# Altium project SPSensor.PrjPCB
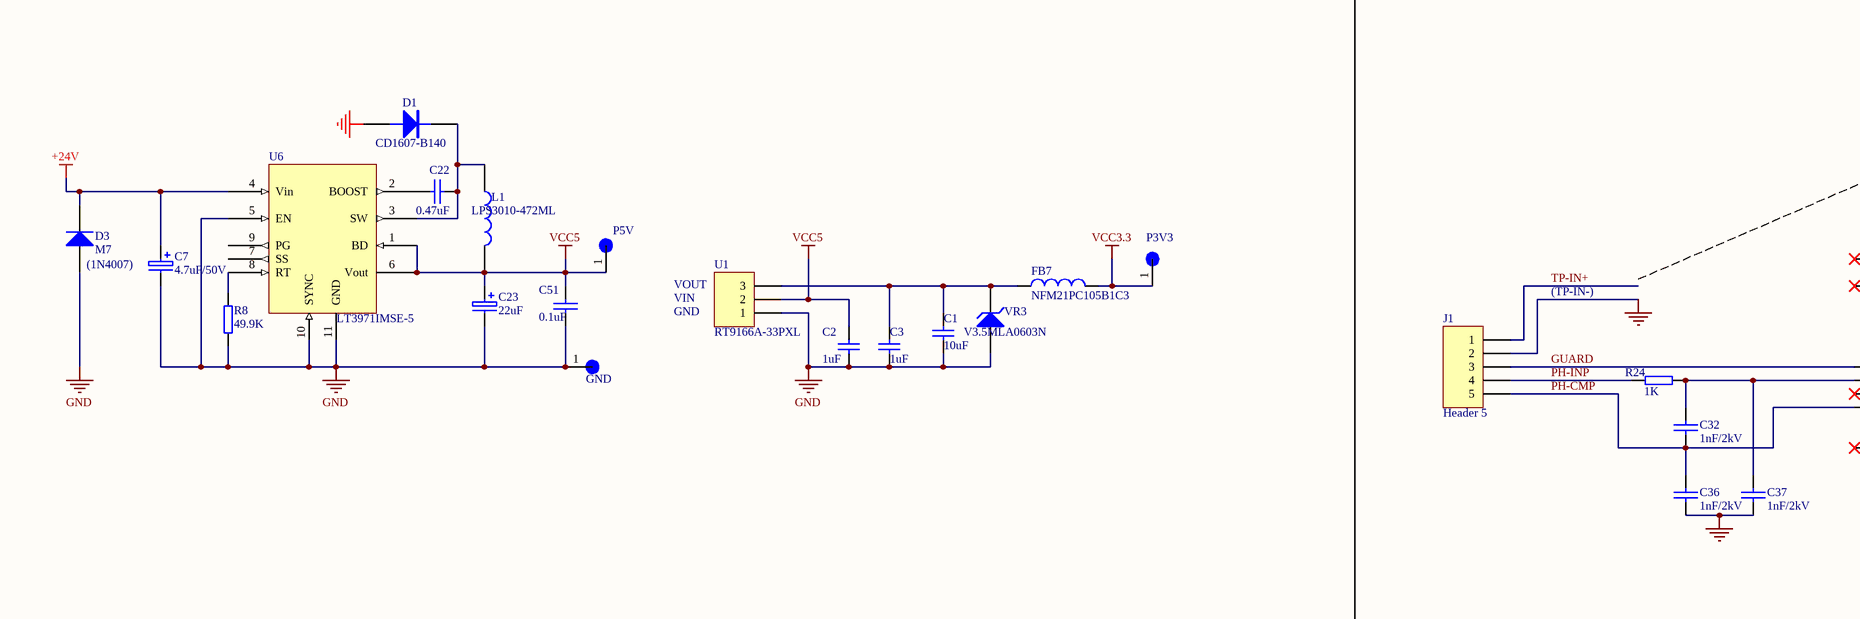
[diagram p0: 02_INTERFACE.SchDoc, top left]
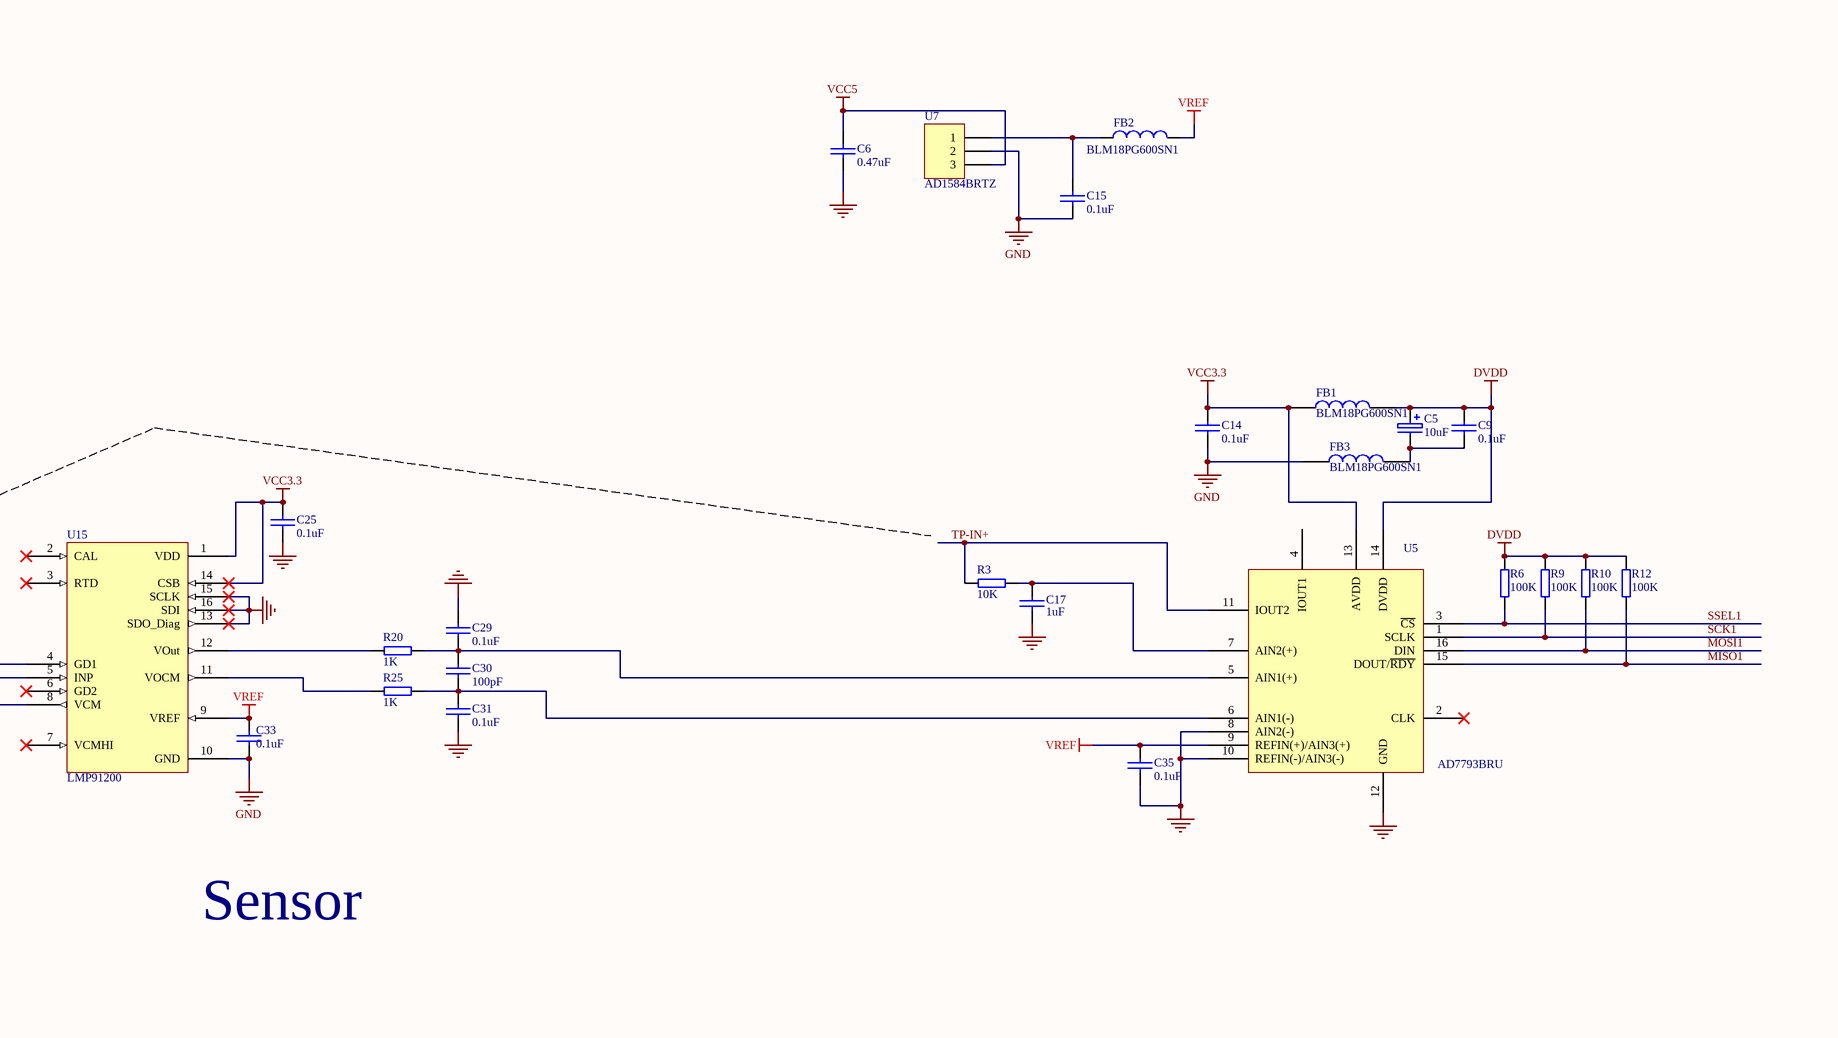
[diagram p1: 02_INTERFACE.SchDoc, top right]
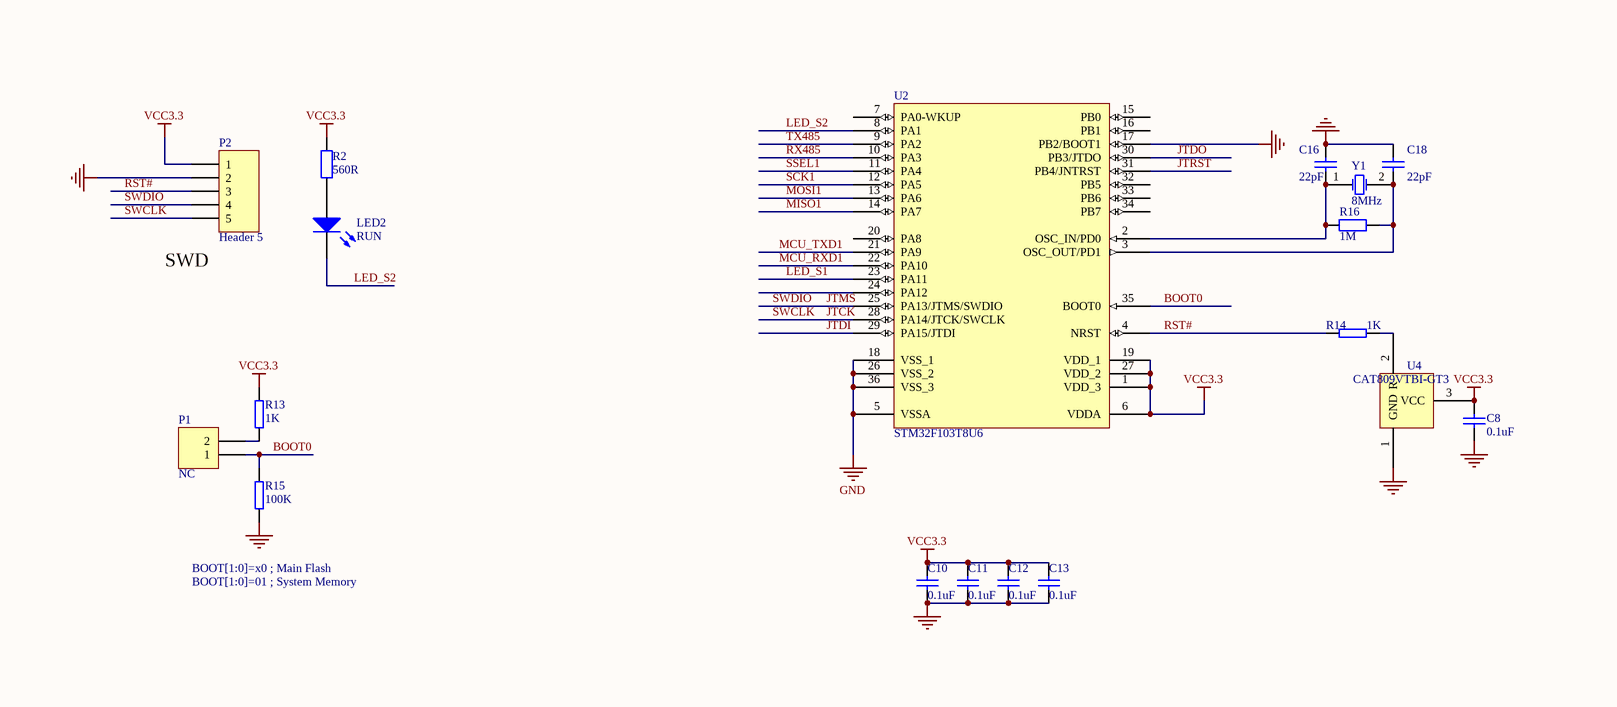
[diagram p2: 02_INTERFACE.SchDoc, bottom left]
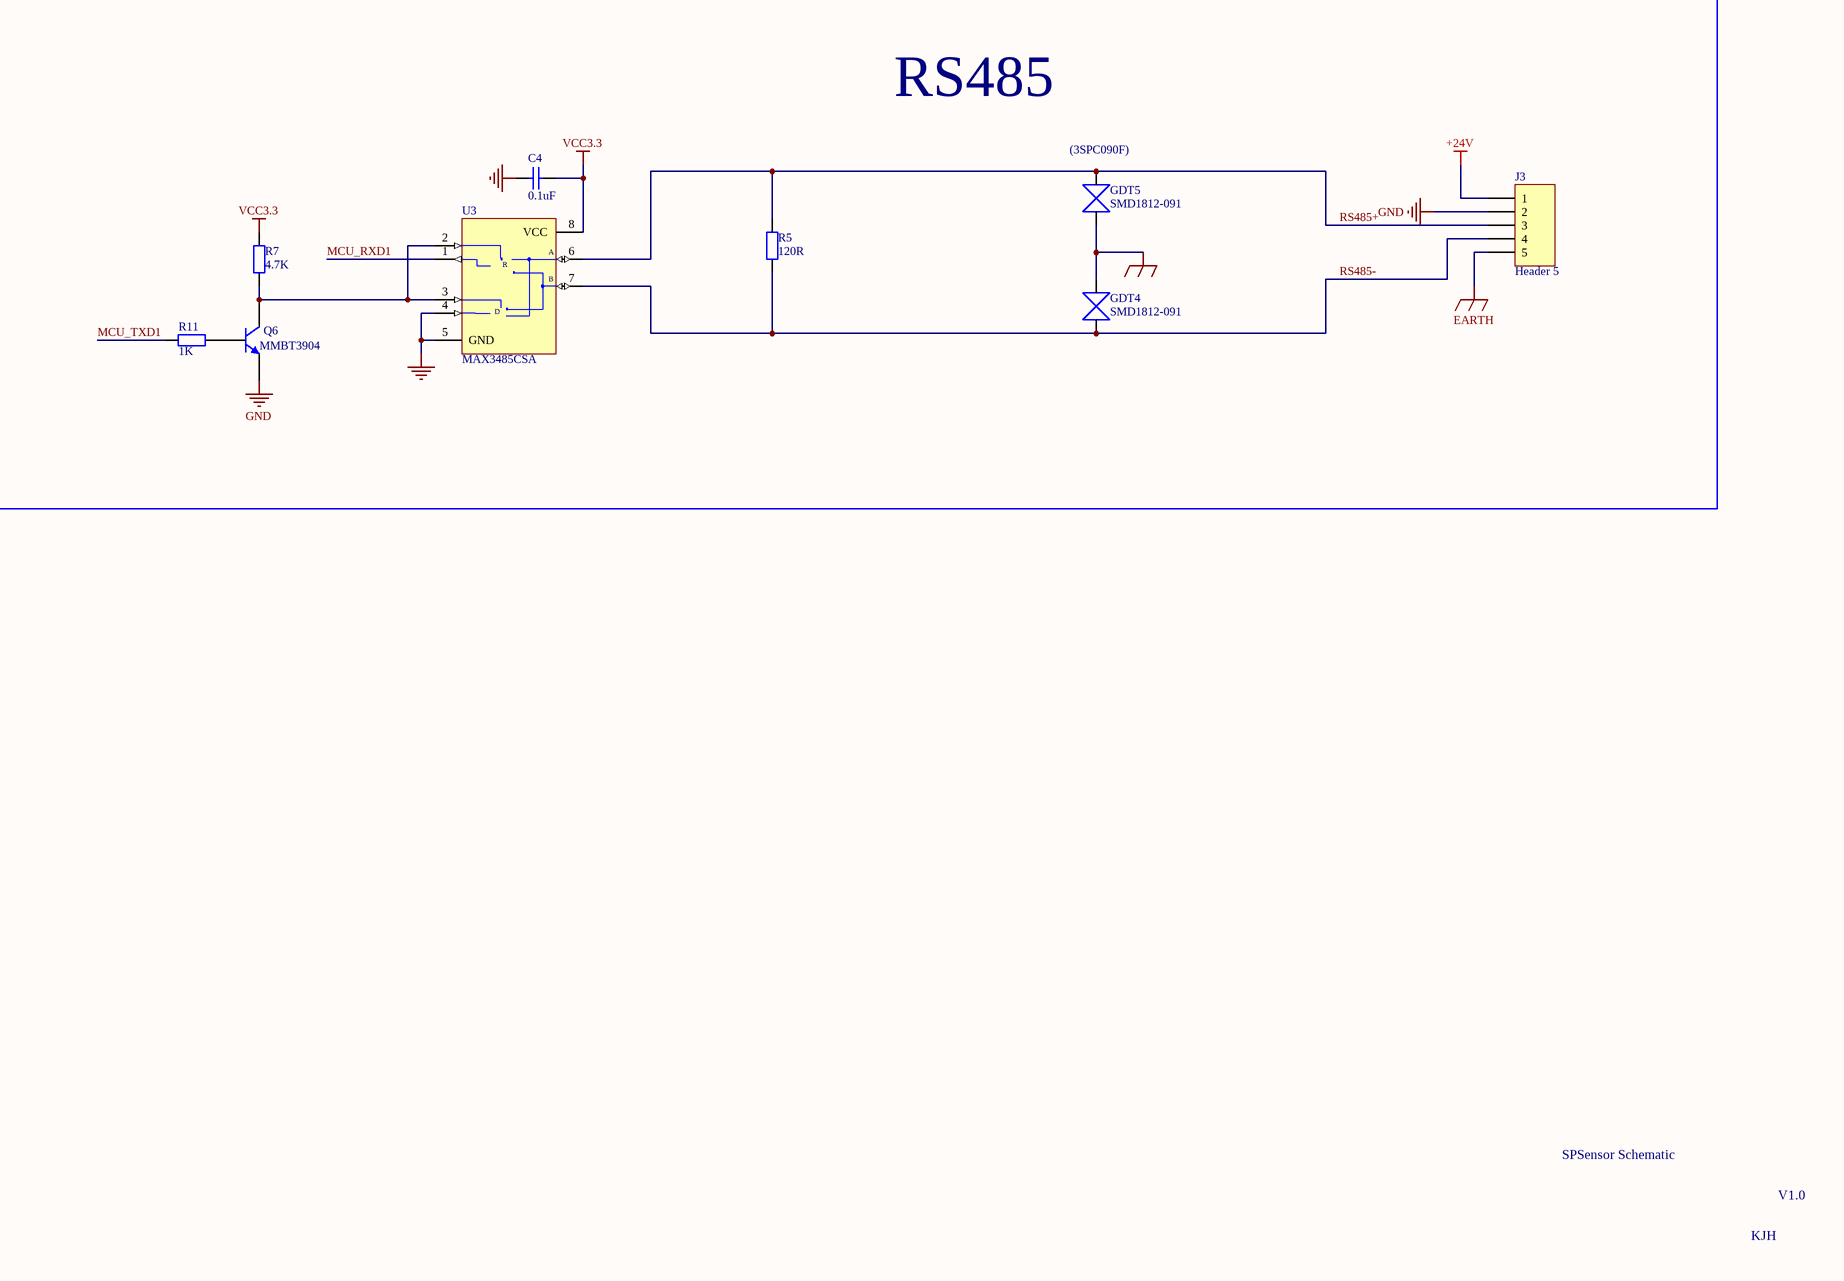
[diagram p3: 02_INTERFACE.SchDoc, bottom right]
1 sheet, 75 parts. Net scope: global (net labels, ports and power ports of the same name join across sheets).
Board file: SPSensor V0.1.PcbDoc

## Sheet 02_INTERFACE.SchDoc
size D; SheetNumber: 0; SheetTotal: 0

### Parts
C1  10uF  [SM1206]
C2  1uF  [SM0603]
C3  1uF  [SM0603]
C4  0.1uF  [0603A]
C5  10uF  [SM1206]
C6  0.47uF  [SM0603]
C7  4.7uF/50V  [SM1206]
C8  0.1uF  [0603A]
C9  0.1uF  [0603A]
C10  0.1uF  [SM0603]
C11  0.1uF  [SM0603]
C12  0.1uF  [SM0603]
C13  0.1uF  [SM0603]
C14  0.1uF  [0603A]
C15  0.1uF  [SM0603]
C16  22pF  [SM0603]
C17  1uF  [0603A]
C18  22pF  [SM0603]
C22  0.47uF  [SM0603]
C23  22uF  [SM1206]
C25  0.1uF  [0603A]
C29  0.1uF  [0603A]
C30  100pF  [0603A]
C31  0.1uF  [0603A]
C32  1nF/2kV  [SM1206]
C33  0.1uF  [0603A]
C35  0.1uF  [0603A]
C36  1nF/2kV  [SM1206]
C37  1nF/2kV  [SM1206]
C51  0.1uF  [SM0603]
D1  CD1607-B140  [1206D]
D3  M7  [1206D]
FB1  BLM18PG600SN1  [0603A]
FB2  BLM18PG600SN1  [SM0603]
FB3  BLM18PG600SN1  [0603A]
FB7  NFM21PC105B1C3  [NFM21PC105]
GDT4  SMD1812-091  [1812]
GDT5  SMD1812-091  [1812]
GND  TestPoint  [test point]  (value not drawn)
J1  Header 5  [HDR1X5]
J3  Header 5  [HDR1X5]
L1  LPS3010-472ML  [LPS3010]
LED2  RUN  [SM0805]
P1  NC  [SM0603]
P2  Header 5  [HDR1X3-2.54mm-smd]
P3V3  TestPoint  [test point]  (value not drawn)
P5V  TestPoint  [test point]  (value not drawn)
Q6  MMBT3904  [SOT23_N]
R2  560R  [SM0603]
R3  10K  [0603A]
R5  120R  [SM0603]
R6  100K  [0603A]
R7  4.7K  [SM0603]
R8  49.9K  [SM0603]
R9  100K  [0603A]
R10  100K  [0603A]
R11  1K  [SM0603]
R12  100K  [0603A]
R13  1K  [0603A]
R14  1K  [0603A]
R15  100K  [0603A]
R16  1M  [SM0603]
R20  1K  [0603A]
R24  1K  [0603A]
R25  1K  [0603A]
U1  RT9166A-33PXL  [SOT89L]
U2  STM32F103T8U6  [VFQN36_V]
U3  MAX3485CSA  [NSO8_N]
U4  CAT809VTBI-GT3  [SOT-23]
U5  AD7793BRU  [AD7793]
U6  LT3971IMSE-5  [LT3971]
U7  AD1584BRTZ  [SOT-23]
U15  LMP91200  [LMP91200]
VR3  V3.5MLA0603N  [SM0603]
Y1  8MHz  [CY5.4X4.6]

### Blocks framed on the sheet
Sensor: C5 C6 C9 C14 C15 C17 C25 C29-C33 C35-C37 FB1-FB3 J1 R3 R6 R9 R10 R12 R20 R24 R25 U5 U7 U15
RS485: C4 GDT4 GDT5 J3 Q6 R5 R7 R11 U3

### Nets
+24V: C7.1 D3.2(K) J3.1 U6.4(Vin)
DVDD: C5.1 C9.1 FB1.2 R6.1 R9.1 R10.1 R12.1 U5.14(DVDD)
EARTH: GDT4.2 GDT5.1 J3.5
GND: C1.1 C2.1 C3.1 C4.2 C6.2 C7.2 C8.2 C10.2 C11.2 C12.2 C13.2 C14.2 C15.2 C16.2 C17.2 C18.2 C23.2 C25.2 C29.1 C31.2 C33.2 C35.2 C36.2 C37.2 C51.2 D1.1(A) D3.1(A) FB3.1 GND.1 J1.2 J3.2 P2.2 Q6.2(E) R8.1 R15.1 U1.1 U2.5(VSSA) U2.17(PB2/BOOT1) U2.18(VSS_1) U2.26(VSS_2) U2.36(VSS_3) U3.4(DI) U3.5(GND) U4.1(GND) U5.8(AIN2(-)) U5.10(REFIN(-)/AIN3(-)) U5.12(GND) U6.5(EN) U6.10(SYNC) U6.11(GND) U7.2 U15.10(GND) U15.13(SDO_Diag) U15.15(SCLK) U15.16(SDI) VR3.1(A)
VCC3.3: C4.1 C8.1 C10.1 C11.1 C12.1 C13.1 C14.1 C25.1 FB1.1 FB7.2 P2.1 P3V3.1 R2.1 R7.2 R13.1 U2.1(VDD_3) U2.6(VDDA) U2.19(VDD_1) U2.27(VDD_2) U3.8(VCC) U4.3(VCC) U5.13(AVDD) U15.1(VDD) U15.14(CSB)
VCC5: C2.2 C6.1 C23.1 C51.1 L1.2 P5V.1 U1.2 U6.1(BD) U6.6(Vout) U7.3
VREF: C33.1 C35.1 FB2.2 U5.9(REFIN(+)/AIN3(+)) U15.9(VREF)
BOOT0: P1.1 R15.2 U2.35(BOOT0)
GUARD: J1.3 U15.4(GD1)
JTCK: P2.5 U2.28(PA14/JTCK/SWCLK)  [also labelled SWCLK]
JTDI: U2.29(PA15/JTDI)
JTDO: U2.30(PB3/JTDO)
JTMS: P2.4 U2.25(PA13/JTMS/SWDIO)  [also labelled SWDIO]
JTRST: U2.31(PB4/JNTRST)
LED_S1: U2.23(PA11)
LED_S2: LED2.2(K) U2.8(PA1)
MCU_RXD1: U2.22(PA10) U3.1(RO)
MCU_TXD1: R11.1 U2.21(PA9)
MISO1: R12.2 U2.14(PA7) U5.15(DOUT/~{RDY})
MOSI1: R10.2 U2.13(PA6) U5.16(DIN)
PH-CMP: C32.2 C36.1 J1.5 U15.8(VCM)
PH-INP: J1.4 R24.1
RS485+: GDT5.2 J3.3 R5.2 U3.6(A)
RS485-: GDT4.1 J3.4 R5.1 U3.7(B)
RST#: P2.3 R14.2 U2.4(NRST)
RX485: U2.10(PA3)
SCK1: R9.2 U2.12(PA5) U5.1(SCLK)
SSEL1: R6.2 U2.11(PA4) U5.3(~{CS})
TP-IN+: J1.1 R3.1 U5.11(IOUT2)
TX485: U2.9(PA2)
NetC1_2: C1.2 C3.2 FB7.1 U1.3 VR3.2(K)
NetC5_2: C5.2 C9.2 FB3.2
NetC15_1: C15.1 FB2.1 U7.1
NetC16_1: C16.1 R16.1 U2.2(OSC_IN/PD0) Y1.1(OSC1)
NetC17_1: C17.1 R3.2 U5.7(AIN2(+))
NetC18_1: C18.1 R16.2 U2.3(OSC_OUT/PD1) Y1.2(OSC2)
NetC22_1: C22.1 U6.2(BOOST)
NetC22_2: C22.2 D1.2(K) L1.1 U6.3(SW)
NetC29_2: C29.2 C30.1 R20.2 U5.5(AIN1(+))
NetC30_2: C30.2 C31.1 R25.2 U5.6(AIN1(-))
NetC32_1: C32.1 C37.1 R24.2 U15.5(INP)
NetLED2_1: LED2.1(A) R2.2
NetP1_2: P1.2 R13.2
NetQ6_1: Q6.1(B) R11.2
NetQ6_3: Q6.3(C) R7.1 U3.2(~{RE}) U3.3(DE)
NetR8_2: R8.2 U6.8(RT)
NetR14_1: R14.1 U4.2(R)
NetR20_1: R20.1 U15.12(VOut)
NetR25_1: R25.1 U15.11(VOCM)

Not connected (* = marked no-connect by the designer): U2 7(PA0-WKUP) 15(PB0) 16(PB1) 20(PA8) 24(PA12) 32(PB5) 33(PB6) 34(PB7); U5 2(CLK)* 4(IOUT1); U6 7(SS) 9(PG); U15 2(CAL)* 3(RTD)* 6(GD2)* 7(VCMHI)*

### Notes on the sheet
- (1N4007)
- VOUT
- GND
- VIN
- (TP-IN-)
- (near GDT5) (3SPC090F)
- (near P2) SWD
- BOOT[1:0]=x0 ; Main Flash
- BOOT[1:0]=01 ; System Memory
- SPSensor Schematic
- KJH
- V1.0

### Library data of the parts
C1-C3 C16 C18 = Cap: Capacitor; Value: 0.1uF
C4 C8 = Cap: Capacitor, X7R Ceramic
C5 = CAPE: 极性电容
C6 C9 C14 C15 C22 C25 C29-C33 C35-C37 C51 = CAP: Capacitor
C7 C23 = C: 极性电容
C10-C13 = Cap: Capacitor
C17 = C: 电容
D1 = DIODE
D3 = Diode 1N4007: 1 Amp General Purpose Rectifier
FB1 FB3 L1 = INDUCTOR
FB2 FB7 = Inductor: Code_IEC: 1005; Value: 10mH
GDT4 GDT5 = BT90
J1 J3 P2 = Header 5: Header, 5-Pin
LED2 = LED0: Typical INFRARED GaAs LED
P1 = Head: Header, 2-Pin, 2.54mm, 排针
Q6 = MMBT3904: NPN Switching Transistor
R2 R5 R7 R16 = Res2: Resistor; Value: 1K
R3 R6 R9 R10 R12 R20 R24 R25 = R: 电阻
R8 R13-R15 = RES: 电阻
R11 = Res2: Resistor
U1 = Header 3: Header, 3-Pin
U2 = STM32F103T8U6: STM32 ARM-based 32-bit MCU with 64 Kbytes Flash, 36-pin VFQFPN, Industrial Temperature
U3 = MAX485CSA: Low-Power, Slew-Rate-Limited RS-485/RS-422 Transceiver
U4 = CAT809: Onsemi RESET
U5 = AD7793
U6 = LT3971
U7 = Header 3: 4.096V reference
VR3 = D Zener: Zener Diode
Y1 = XTAL: Crystal Oscillator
